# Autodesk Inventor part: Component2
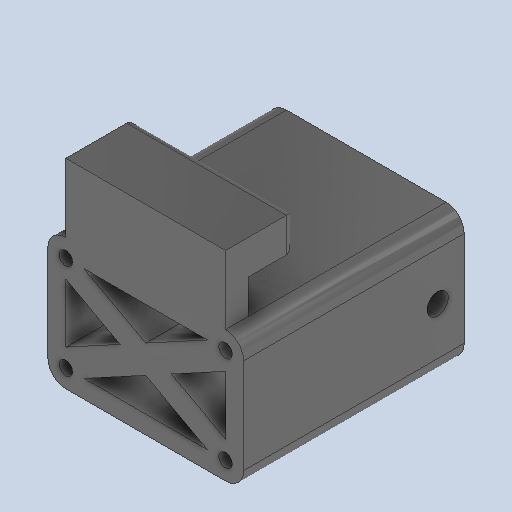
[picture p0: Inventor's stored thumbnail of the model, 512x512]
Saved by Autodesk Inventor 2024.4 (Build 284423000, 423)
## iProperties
Created: 2025-07
Part Number: Component2
Material: Generic
Document SubType Name: Modeling
Designer: AdminForWorker
Density: 1 g/cm^3
Appearance: Default
Title: Component2
Author: AdminForWorker
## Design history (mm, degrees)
feature "Body1"
body "Solid1"
